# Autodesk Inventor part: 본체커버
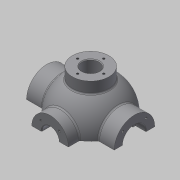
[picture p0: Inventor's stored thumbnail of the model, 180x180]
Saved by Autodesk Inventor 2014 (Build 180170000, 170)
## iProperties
Created: 2015-12
Part Number: 본체커버
Material: 일반
Document SubType Name: Modeling
Designer: mduedu
Density: 1 g/cm^3
Mass: 211.839 g
Surface Area: 451.737 cm^2
Volume: 211.839 cm^3
Appearance: 기본값
Author: mduedu
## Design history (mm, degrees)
sketch "스케치1"
  geometry: L1 (-53, 0)-(53, 0); A1 r 53 centre (0, 0) between (53, 0) and (-53, 0); 2 further points
  constraints: 2 coincident, 2 end point, 2 point on circle, 1 centre point, 1 horizontal, 1 midpoint
  dimensions: "d0" = 53 radius of A1
revolve "회전1" sketch "스케치1" stored, may be unused: angle "d2" = 90 deg
feature "쉘1" dims "d11" = 10
node "작업 평면1"
sketch "스케치2"
  geometry: C1 r 31 at (0, 0); 1 further point
  constraints: 1 centre point, 1 coincident
  dimensions: "d4" = 62 diameter of C1
extrude "돌출1" join sketch "스케치2" stored distance "d5" = 10; taper "d6" = 0 deg
node "작업 평면2"
sketch "스케치3"
  geometry: C1 r 28 at (0, 0); 1 further point
  constraints: 1 centre point, 1 coincident
  dimensions: "d8" = 56 diameter of C1
extrude "돌출2" join sketch "스케치3" stored distance "d9" = 10; taper "d10" = 0 deg
hole "구멍1" diameter "d14" = 35; stored, may be unused: countersink angle "d18" = 90 deg, drill point angle "d20" = 0 deg; dims "d12" = 10, "d13" = 10, "d15" = 6, "d16" = 4, "d17" = 2, "d19" = 16
hole "구멍2" diameter "d23" = 27; stored, may be unused: countersink angle "d27" = 90 deg, drill point angle "d29" = 0 deg; dims "d21" = 10, "d22" = 10, "d24" = 6, "d25" = 4, "d26" = 2, "d28" = 16
fillet "모깎기1" dims "d30" = 0.3
hole "구멍3" diameter "d33" = 26; stored, may be unused: countersink angle "d37" = 90 deg, drill point angle "d39" = 0 deg; dims "d31" = 10, "d32" = 10, "d34" = 6, "d35" = 4, "d36" = 2, "d38" = 16
chamfer "모따기1" distance "d40" = 1; stored, may be unused: second distance "d41" = 2, angle "d42" = 45 deg
sketch "스케치4"
  geometry: L1 (0, 0)-(0, -25); L2 (0, 0)-(-17.678, -17.678); A1 r 25 centre (0, 0) between (-17.678, -17.678) and (0, -25); 1 further point
  constraints: 4 end point, 2 point on circle, 1 centre point, 1 coincident, 1 vertical
  dimensions: "d43" = 50 diameter of A1; "d47" = 45 deg angle of L1 L2
hole "구멍4" sketch "스케치4" at (-17.678, -17.678) diameter "d49" = 3.242; stored, may be unused: countersink angle "d53" = 90 deg, drill point angle "d55" = 118 deg; dims "d50" = 11, "d51" = 4, "d52" = 2, "d54" = 13
sketch "스케치5"
  geometry: L1 (0, 0)-(0, -20); L2 (0, 0)-(-14.142, -14.142); A1 r 20 centre (0, 0) between (0, -20) and (-14.142, -14.142); 2 further points
  constraints: 4 end point, 2 coincident, 2 point on circle, 1 centre point, 1 vertical
  dimensions: "d59" = 40 diameter of A1; "d65" = 45 deg angle of L1 L2
hole "구멍5" sketch "스케치5" at (-14.142, -14.142) diameter "d67" = 3.242; stored, may be unused: countersink angle "d71" = 90 deg, drill point angle "d73" = 118 deg; dims "d68" = 8, "d69" = 4, "d70" = 2, "d72" = 10
node "작업 평면3"
sketch "스케치6"
  geometry: C1 r 65 at (0, 0); 1 further point
  constraints: 1 centre point, 1 coincident
  dimensions: "d78" = 130 diameter of C1
extrude "돌출3" join sketch "스케치6" distance "d80" = 10; taper "d81" = 0 deg
sketch "스케치7"
  geometry: C1 r 20 at (0, 0); 1 further point
  constraints: 1 centre point, 1 coincident
  dimensions: "d82" = 40 diameter of C1
extrude "돌출4" join sketch "스케치7" stored distance "d84" = 10; taper "d85" = 0 deg
sketch "스케치8"
  geometry: 2 further points
  constraints: 1 coincident
hole "구멍6" sketch "스케치8" at (0, 0) diameter "d86" = 20; stored, may be unused: countersink angle "d90" = 90 deg, drill point angle "d92" = 118 deg; dims "d87" = 7, "d88" = 40, "d89" = 5, "d91" = 10
fillet "모깎기2" dims "d93" = 0.3
sketch "스케치9"
  geometry: L1 (65, -75)-(-65, -75) reference; L2 (-45, -75)-(-38.245, -36.692); A1 r 53 centre (0, 0) between (42.988, 31) and (42.988, -31) reference; 1 further point
  constraints: 2 end point, 1 point on circle, 1 point on line
  dimensions: "d94" = 45 horizontal distance of L2.start point (0, 0); "d95" = 80 deg angle of L2 L1
feature "리브1" sketch "스케치9" dims "d96" = 1, "d97" = 8, "d98" = 0, "d99" = 0, "d100" = 1, "d101" = 1
sketch "스케치10"
  geometry: L1 (0, 0)-(0, -55); L2 (0, 0)-(-38.891, -38.891); A1 r 55 centre (0, 0) between (0, -55) and (-38.891, -38.891); 2 further points
  constraints: 4 end point, 2 coincident, 2 point on circle, 1 centre point, 1 vertical
  dimensions: "d105" = 110 diameter of A1; "d107" = 45 deg angle of L1 L2
hole "구멍7" sketch "스케치10" at (-38.891, -38.891) diameter "d109" = 10; stored, may be unused: countersink angle "d113" = 90 deg, drill point angle "d115" = 118 deg; dims "d110" = 7, "d111" = 40, "d112" = 5, "d114" = 10
fillet "모깎기3" dims "d120" = 3
fillet "모깎기4" dims "d121" = 3, "d122" = 3
fillet "모깎기5" dims "d123" = 3
fillet "모깎기6" dims "d124" = 3
sketch "스케치11"
  geometry: C1 r 5 at (-38.891, 38.891) reference; C2 r 5 at (38.891, 38.891) reference; C3 r 5 at (38.891, -38.891) reference; C4 r 5 at (-38.891, -38.891) reference; C5 r 20 at (0, 0) reference; C6 r 65 at (0, 0) reference; 1 further point
  constraints: 3 other
feature "엠보싱1" sketch "스케치11" dims "d125" = 0.5, "d126" = 0
sketch "스케치12"
  geometry: L1 (0, 100)-(0, -100); L2 (0, 100)-(-150, 100); L3 (-150, 100)-(-150, -100); L4 (-150, -100)-(0, -100); 2 further points
  constraints: 8 end point, 3 perpendicular, 1 coincident, 1 midpoint, 1 vertical
  dimensions: "d127" = 200 distance of L2.end L3.end; "d129" = 150 distance of L3.end L1.end
extrude "돌출5" cut sketch "스케치12" stored distance "d130" = 10; taper "d131" = 0 deg
sketch "스케치13"
  geometry: C1 r 7 at (0, -53); A1 r 53 centre (0, 0) between (-42.113, -32.179) and (42.113, -32.179) reference; 1 further point
  constraints: 1 centre point, 1 point on circle
  dimensions: "d132" = 14 diameter of C1
extrude "돌출6" join sketch "스케치13" distance "d133" = 5; taper "d134" = 0 deg
sketch "스케치14"
  geometry: C1 r 7 at (0, 0) reference; 1 further point
extrude "돌출7" cut sketch "스케치14" stored distance "d135" = 5; taper "d136" = 0 deg
sketch "스케치15"
  geometry: C1 r 2.25 at (0, 53); A1 r 7 centre (0, 53) between (6.965, 52.302) and (-6.965, 52.302) reference; 1 further point
  constraints: 1 centre point, 1 coincident
  dimensions: "d139" = 4.5 diameter of C1
extrude "돌출8" cut sketch "스케치15" stored distance "d141" = 5; taper "d142" = 0 deg
fillet "모깎기7" dims "d143" = 3
fillet "모깎기8" dims "d144" = 1
fillet "모깎기9" dims "d145" = 1
fillet "모깎기10" dims "d146" = 1
node "작업 평면4"
sketch "스케치16"
  geometry: C1 r 28 at (0, 0); 1 further point
  constraints: 1 centre point, 1 coincident
  dimensions: "d148" = 56 diameter of C1
extrude "돌출9" join sketch "스케치16" stored distance "d150" = 5; taper "d151" = 0 deg
hole "구멍8" diameter "d154" = 26; stored, may be unused: countersink angle "d158" = 90 deg, drill point angle "d160" = 118 deg; dims "d152" = 10, "d153" = 10, "d155" = 6, "d156" = 4, "d157" = 2, "d159" = 8
sketch "스케치17" dims "d161" = 40
  geometry: 3 further points
  constraints: 2 vertical alignment, 1 coincident, 2 other
hole "구멍9" sketch "스케치17" at (0, 20) diameter "d163" = 3.242; stored, may be unused: countersink angle "d167" = 90 deg, drill point angle "d169" = 118 deg; dims "d164" = 8, "d165" = 4, "d166" = 2, "d168" = 10
fillet "모깎기11" dims "d173" = 3
chamfer "모따기2" distance "d174" = 1; stored, may be unused: second distance "d175" = 2, angle "d176" = 45 deg
node "솔리드1"
mirror "대칭1"
mirror "대칭2"
pattern_circular "원형 패턴1" dims angle "d57" = 360 deg
mirror "대칭3"
pattern_circular "원형 패턴2" dims angle "d75" = 360 deg
pattern_circular "원형 패턴3" dims angle "d103" = 360 deg
pattern_circular "원형 패턴4" dims angle "d118" = 360 deg
pattern_circular "원형 패턴5" dims angle "d171" = 360 deg
node "투영된 루프1"
other parameters: "d3" = 67, "d7" = 62, "d77" = -85, "d147" = 62
